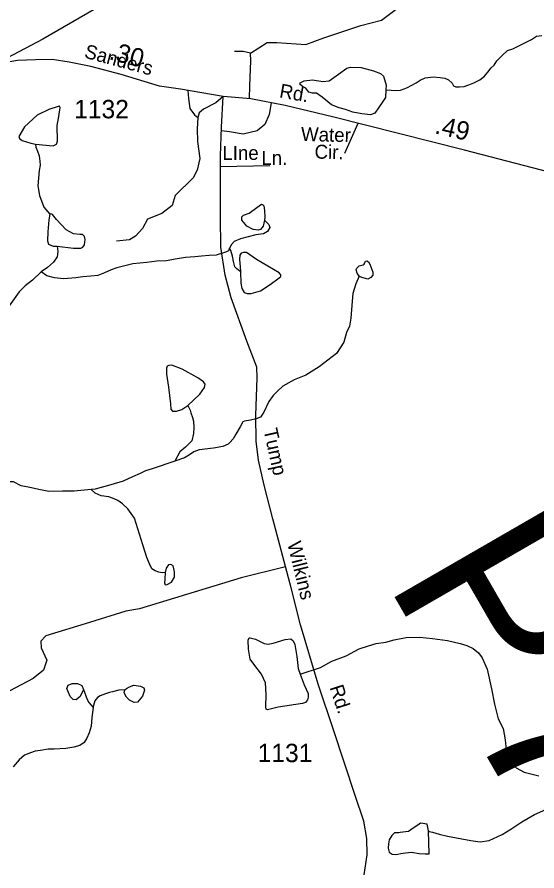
# Model space of a CAD drawing. Extents: x 2056842 to 2160602, y 826753 to 1016856.
# Drawn here: x 2087343 to 2090876, y 890342 to 896145 of the extents above; entities that cross this region are included whole.
import ezdxf

# ---------------------------------------------------------------- set-up
doc = ezdxf.new("R2010")
doc.units = 0
for name, color, linetype in [('Exist Hydrographic Creek Single Shore', 7, 'Continuous'), ('Exist Hydrographic Misc Water Feature', 7, 'Continuous'), ('Exist Road Non-System Type 51', 7, 'Continuous'), ('Exist Road Non-System Type 51 Label', 7, 'Continuous'), ('Exist Road Secondary Mileage Hundredths English Label', 7, 'Continuous'), ('Exist Road Secondary Structure Pipe Number Label', 7, 'Continuous'), ('Exist Road Secondary Type 51 Attributed', 7, 'Continuous'), ('Exist Road Secondary Type 51 Label', 7, 'Continuous'), ('Exist Road Secondary Type 51 Number Label', 7, 'Continuous')]:
    doc.layers.add(name, color=color, linetype=linetype)

msp = doc.modelspace()

# ---------------------------------------------------------------- linework, layer by layer
at = {"layer": 'Exist Hydrographic Creek Single Shore'}
for points in [[(2087467.1, 895281.8), (2087471, 895261.8), (2087481.1, 895233.8), (2087493.2, 895201.6), (2087497.5, 895165.6), (2087499.5, 895137.7), (2087493.6, 895101.7), (2087482.6, 894998.4), (2087495.1, 894932.3), (2087525, 894853.7), (2087566.2, 894805)], [(2087614.8, 894589.1), (2087725.9, 894575.3), (2087775.8, 894574.1), (2087789.5, 894581.6), (2087800.7, 894597.8), (2087805.7, 894634), (2087800.7, 894654), (2087787, 894666.4), (2087768.3, 894666.4), (2087725.9, 894672.7), (2087676, 894700.1), (2087611.1, 894768.8), (2087583.6, 894803.7), (2087571.2, 894808.7), (2087566.2, 894805)], [(2087614.8, 894589.1), (2087619.8, 894552.9), (2087614.8, 894515.4), (2087591.1, 894478.7), (2087550, 894442.5), (2087506.3, 894413.8)], [(2088787, 894573.6), (2088779, 894555.8), (2088766.9, 894550), (2088745.2, 894541.9), (2088695.2, 894527.5), (2088647.4, 894525.5), (2088595.3, 894519.1), (2088551.2, 894515.2), (2088487.3, 894510.8), (2088417.1, 894498.7), (2088357.2, 894488.7), (2088293.3, 894486.2), (2088225.6, 894478.2), (2088129.4, 894467.6), (2088021.4, 894441.4), (2087981.8, 894427.6), (2087937.5, 894407.5), (2087891.6, 894389.2), (2087843.4, 894383.2), (2087789.9, 894380.7), (2087741.9, 894372.6), (2087657.2, 894366.4), (2087596.1, 894372.6), (2087543.7, 894386.4), (2087506.3, 894413.8)], [(2087506.3, 894413.8), (2087447.7, 894356.4), (2087397, 894318.2), (2087357.1, 894278.3), (2087288.5, 894182.2), (2087262.3, 894139.7), (2087220.9, 893995), (2087205.3, 893934.9), (2087189.5, 893870.7), (2087172.5, 893820.2), (2087144.3, 893767)], [(2089667.1, 894384.4), (2089644.7, 894331.9), (2089624.7, 894265.8), (2089619.7, 894214.4), (2089612.2, 894098.3), (2089602.3, 894044.3), (2089582.6, 894000.2), (2089563.2, 893936.1), (2089513.1, 893858.1), (2089396.7, 893767.3), (2089305.6, 893712.4), (2089227, 893679.9), (2089149.7, 893636.2), (2089112, 893602.8), (2089082.3, 893572.8), (2089054.4, 893532.8), (2089020.4, 893458.9), (2088996.8, 893426.7), (2088968.3, 893414.4), (2088928.9, 893404.5), (2088888.7, 893398.5), (2088876.6, 893394.2), (2088858.6, 893360.5), (2088829.1, 893310.1), (2088811, 893277.9), (2088789.1, 893254.1), (2088777.4, 893242), (2088741.1, 893225.6), (2088677.3, 893215.9), (2088581.4, 893203.2), (2088543.2, 893191.2), (2088513.7, 893169.2), (2088479.6, 893148.7), (2088415.9, 893126.2)], [(2087846.3, 892933.2), (2087730.2, 892922.8), (2087650.2, 892922.4), (2087558.2, 892920.1), (2087502.4, 892932.2), (2087430.2, 892947), (2087370.3, 892959.5), (2087319.2, 892985.7), (2087273, 892986.9), (2087230.6, 892968.2), (2087206.9, 892957), (2087139.6, 892976.9), (2087061, 893035.6), (2087029.8, 893053.1), (2086968, 893066.3), (2086820.5, 893090.3)], [(2088415.9, 893126.2), (2088259.8, 893074.2), (2088216, 893060.2), (2088179.7, 893042.1), (2088128, 893020), (2088063.8, 892991.9), (2087980.2, 892965.6), (2087874.1, 892937.1), (2087846.3, 892933.2)], [(2089265.9, 891678.6), (2089404.4, 891724.8), (2089483, 891767.2), (2089579.6, 891804.5), (2089667.5, 891850.8), (2089731.3, 891871.2), (2089783.2, 891887.3), (2089849, 891897.5), (2089905.4, 891911.8), (2089987, 891927.8), (2090080.9, 891930.1), (2090167.2, 891922.3), (2090268.9, 891908.6), (2090353.4, 891887.3), (2090399.2, 891873), (2090443.4, 891853.3), (2090479.3, 891823.5), (2090503.3, 891789.5), (2090537.1, 891714), (2090567, 891580.5), (2090587, 891474.4), (2090613.2, 891374.5), (2090645.6, 891310.9), (2090659.3, 891232.2), (2090669.3, 891141.1), (2090672.6, 891119.4), (2090683.8, 891095.7), (2090734.9, 891043.3), (2090789.8, 891013.3), (2090888.4, 890987.1)], [(2087858.8, 891453.5), (2087851.2, 891385.2), (2087845.4, 891325.2), (2087833.3, 891281.1), (2087817.8, 891243.3), (2087797.7, 891215.1), (2087769.8, 891195), (2087727.7, 891182.7), (2087673.8, 891174.7), (2087593.6, 891168.6), (2087553.6, 891168.6), (2087501.8, 891160.1), (2087465.7, 891155.8), (2087434.1, 891144.1), (2087393.9, 891127.9), (2087355.8, 891097.9), (2087316.4, 891049.5)], [(2090138.9, 890614.7), (2090143.5, 890610.4), (2090167, 890604.8), (2090211.5, 890590.7), (2090269.4, 890579.1), (2090427.2, 890549.5), (2090491.4, 890539.4), (2090551.3, 890549.7), (2090639.3, 890590), (2090698.9, 890626.4), (2090773, 890676.4), (2090860.5, 890724.8), (2090936.8, 890758.8), (2090996.7, 890761), (2091044.7, 890753.3), (2091102.7, 890737), (2091138.9, 890730.7)]]:
    msp.add_lwpolyline(points, dxfattribs=at)
at = {"layer": 'Exist Hydrographic Misc Water Feature'}
for points in [[(2089850.2, 895651.5), (2089921.6, 895645.3), (2089949.5, 895649.4), (2089973.5, 895657.5), (2089997.5, 895665.6), (2090021.5, 895679.6), (2090055.5, 895697.7), (2090083.4, 895715.8), (2090115.4, 895731.9), (2090171.3, 895740.1), (2090219.3, 895734.2), (2090251.3, 895730.2), (2090275.3, 895718.5), (2090299.5, 895696.5), (2090309.3, 895678.5), (2090325.3, 895670.6), (2090349.3, 895670.6), (2090381.5, 895672.7), (2090413.5, 895684.8), (2090447.3, 895698.9), (2090487.3, 895719.1), (2090519.1, 895743.2), (2090543.1, 895771.3), (2090565, 895799.2), (2090584.9, 895819.3), (2090604.8, 895847.4), (2090640.7, 895883.5), (2090676.6, 895917.6), (2090712.5, 895929.8), (2090838.4, 895992.1), (2090874.3, 896016.2), (2090910.4, 896020.4)], [(2089850.2, 895651.5), (2089847.8, 895599), (2089825.3, 895564.1), (2089774.2, 895492.9), (2089744.2, 895480.5), (2089686.8, 895487.9), (2089625.7, 895497.9), (2089575.8, 895517.9), (2089532.1, 895527.9), (2089479.8, 895547.9), (2089417.4, 895601.5), (2089377.5, 895627.7), (2089351.3, 895627.7), (2089325.1, 895635.2), (2089306.4, 895661.4), (2089282.7, 895673.9), (2089265.2, 895690.1), (2089267.7, 895698.9), (2089293.9, 895712.6), (2089350, 895718.9), (2089421.1, 895707.6), (2089464.8, 895711.4), (2089527.2, 895756.3), (2089583.3, 895798.7), (2089609.5, 895805), (2089681.8, 895802.5), (2089764.2, 895778.8), (2089812.8, 895761.3), (2089832.8, 895742.6), (2089851.5, 895681.4), (2089850.2, 895651.5)], [(2087467.1, 895281.8), (2087587.4, 895270.3), (2087609.8, 895281.5), (2087617.3, 895301.5), (2087616.1, 895407.6), (2087626.1, 895468.7), (2087634.8, 895529.9), (2087629.8, 895539.9), (2087622.3, 895537.4), (2087558.7, 895517.4), (2087478.9, 895478.7), (2087394, 895400.1), (2087354.1, 895333.9), (2087357.9, 895320.2), (2087376.6, 895306.5), (2087436.4, 895287.8), (2087467.1, 895281.8)], [(2089024.5, 894764.5), (2089014.5, 894723.1), (2088997, 894701.9), (2088980.8, 894696.9), (2088947.1, 894700.6), (2088904.7, 894723.1), (2088871, 894765.5), (2088869.8, 894788), (2088882.2, 894799.2), (2088919.7, 894813), (2088972, 894850.4), (2089003.2, 894872.9), (2089010.7, 894871.6), (2089019.4, 894861.6), (2089024.4, 894830.4), (2089025.7, 894784.3), (2089024.5, 894764.5)], [(2087566.2, 894805), (2087558.7, 894766.3), (2087552.5, 894686.4), (2087550, 894624), (2087556.2, 894601.5), (2087587.4, 894587.8), (2087614.8, 894589.1)], [(2089024.5, 894764.5), (2089054.4, 894735.8), (2089060.6, 894714.6), (2089044.6, 894688.4), (2089016.9, 894672.7), (2088964.6, 894664.5), (2088912.7, 894652.4), (2088860.7, 894637.9), (2088819, 894620), (2088800.8, 894600), (2088787, 894573.6)], [(2088862.3, 894412.6), (2088845.3, 894428.1), (2088837.5, 894432.1), (2088829.3, 894439.9), (2088823.5, 894448.1), (2088813.3, 894484), (2088806.9, 894519.9), (2088795, 894557.9), (2088787, 894573.6)], [(2088862.3, 894412.6), (2088863.5, 894337.7), (2088869.8, 894300.2), (2088886, 894274), (2088907.2, 894265.3), (2088934.6, 894265.3), (2088998.2, 894285.3), (2089063.1, 894327.7), (2089123, 894372.6), (2089135.5, 894382.6), (2089135.5, 894392.6), (2089124.2, 894406.3), (2088970.8, 894497.4), (2088902.2, 894544.9), (2088881, 894546.1), (2088866, 894541.1), (2088856, 894526.1), (2088854.8, 894497.4), (2088859.8, 894447.5), (2088862.3, 894412.6)], [(2089667.1, 894384.4), (2089653.4, 894405.6), (2089647.2, 894426.8), (2089650.9, 894438), (2089667.1, 894455.5), (2089694.6, 894460.5), (2089702, 894466.7), (2089712, 894486.7), (2089720.8, 894489.2), (2089730.7, 894480.5), (2089739.5, 894465.5), (2089760.7, 894410.6), (2089760.7, 894391.8), (2089747, 894374.4), (2089725.8, 894364.4), (2089687.1, 894374.4), (2089667.1, 894384.4)], [(2088503.3, 893504.4), (2088584.3, 893583), (2088616.8, 893626.7), (2088621.8, 893650.4), (2088610.5, 893665.4), (2088571.9, 893692.9), (2088464.6, 893752.8), (2088393.5, 893779), (2088374.8, 893777.8), (2088363.5, 893771.5), (2088358.6, 893759), (2088357.3, 893719.1), (2088372.3, 893629.2), (2088384.8, 893515.6), (2088388.5, 893479.4), (2088398.5, 893467), (2088401, 893467), (2088427.2, 893465.7), (2088462.1, 893477), (2088503.3, 893504.4)], [(2088503.3, 893504.4), (2088519.5, 893473.2), (2088523.2, 893454.5), (2088534.4, 893423.3), (2088540.7, 893399.6), (2088544.4, 893355.9), (2088541.9, 893315.9), (2088529.5, 893264.8), (2088487, 893222.3), (2088448.4, 893191.1), (2088415.9, 893126.2)], [(2088348.8, 892369.3), (2088329.8, 892368.5), (2088305.8, 892372.5), (2088282, 892380.6), (2088258, 892394.4), (2088242, 892428.5), (2088225.6, 892472.4), (2088196.6, 892559.1), (2088164.2, 892667.7), (2088141.8, 892738.8), (2088094.8, 892801.8), (2088058.3, 892835.7), (2088028.3, 892859.7), (2088002.7, 892871.7), (2087966.2, 892885.4), (2087914.1, 892891.3), (2087874.1, 892909.1), (2087846.3, 892933.2)], [(2088348.8, 892369.3), (2088347.6, 892325.7), (2088345.1, 892299.4), (2088350.1, 892287), (2088363.8, 892288.2), (2088392.5, 892304.4), (2088413.7, 892338.1), (2088413.7, 892374.3), (2088403.7, 892414.3), (2088387.5, 892424.3), (2088372.5, 892421.8), (2088355.1, 892399.3), (2088348.8, 892369.3)], [(2089265.9, 891678.6), (2089294.6, 891606.2), (2089320.8, 891547.5), (2089322.1, 891523.8), (2089317.1, 891503.8), (2089303.4, 891486.4), (2089283.4, 891478.9), (2089116.3, 891453.9), (2089043.9, 891436.4), (2089036.4, 891440.2), (2089032.7, 891456.4), (2089036.4, 891540), (2089030.2, 891621.2), (2089004, 891678.6), (2088951.6, 891746), (2088926.6, 891780.9), (2088915.4, 891848.3), (2088914.2, 891909.5), (2088920.4, 891927), (2088926.6, 891927), (2088962.8, 891917), (2089022.7, 891888.3), (2089048.9, 891883.3), (2089083.8, 891889.5), (2089164.9, 891914.5), (2089203.6, 891918.2), (2089219.8, 891905.7), (2089231, 891880.8), (2089244.7, 891799.7), (2089252.2, 891718.5), (2089265.9, 891678.6)], [(2087794.4, 891575.2), (2087772.3, 891526.3), (2087743.6, 891503.9), (2087723.6, 891506.4), (2087702.4, 891526.3), (2087679.9, 891581.3), (2087689.9, 891605), (2087716.1, 891615), (2087752.3, 891616.2), (2087783.5, 891602.5), (2087794.4, 891575.2)], [(2087794.4, 891575.2), (2087818.8, 891507), (2087830.7, 891487.3), (2087846.9, 891469.4), (2087858.8, 891453.5)], [(2088074.3, 891572.1), (2088034.5, 891570), (2087990.2, 891559.7), (2087970.5, 891553.7), (2087942.8, 891545.3), (2087906.5, 891531.4), (2087888.7, 891521.6), (2087870.7, 891497), (2087862.9, 891465.4), (2087858.8, 891453.5)], [(2088074.3, 891572.1), (2088085.4, 891582.5), (2088106.6, 891593.7), (2088136.5, 891603.7), (2088181.4, 891597.5), (2088203.9, 891586.3), (2088207.6, 891570), (2088195.1, 891528.8), (2088160.2, 891488.9), (2088139, 891486.4), (2088106.6, 891501.4), (2088086.6, 891523.9), (2088070.4, 891552.6), (2088074.3, 891572.1)], [(2090138.9, 890614.7), (2090130.9, 890658.5), (2090085, 890666.3), (2090067, 890652.3), (2090035.2, 890632), (2090003, 890610.1), (2089983.1, 890607.8), (2089947.2, 890603.9), (2089937.6, 890601.8), (2089907, 890599.9), (2089889.4, 890583.5), (2089871.4, 890553.4), (2089867.5, 890525.6), (2089865.8, 890497.4), (2089871.8, 890469.7), (2089891.7, 890455.8), (2089911.5, 890453.5), (2089931.4, 890455.8), (2089951.7, 890460.1), (2089967.7, 890462), (2089983.9, 890464.1), (2090023.7, 890468.2), (2090075.4, 890460.4), (2090116, 890458.4), (2090143.7, 890458.6), (2090138.9, 890614.7)]]:
    msp.add_lwpolyline(points, dxfattribs=at)
at = {"layer": 'Exist Road Non-System Type 51'}
msp.add_line((2088725.1, 895129.6), (2089060.1, 895137.2), dxfattribs=at)
for points in [[(2088929, 895898.9), (2089042.3, 895971.9), (2089109.3, 895973.4), (2089305.9, 895958.5), (2089426.6, 896004.7), (2089679, 896089), (2089820.6, 896124.7), (2089947.2, 896220.1), (2090026.9, 896286.5), (2090080.5, 896302.9)], [(2088929, 895898.9), (2088879.9, 895910.8), (2088820.3, 895910.8)], [(2088922.6, 895591.3), (2088924.6, 895678.3), (2088932, 895846.7), (2088929, 895898.9)], [(2088502.9, 895646.6), (2088506.8, 895591.1), (2088517.2, 895524), (2088548.5, 895480.8), (2088572.3, 895462.9)], [(2088742.6, 895606), (2088694.4, 895562.8), (2088609.5, 895519.6), (2088581.2, 895494.2), (2088572.3, 895462.9)], [(2089069.2, 895562.9), (2089057.1, 895483), (2089027.4, 895416), (2088973.7, 895371.2), (2088878.4, 895348.9), (2088787.5, 895365.3), (2088731.7, 895371.5)], [(2088572.3, 895462.9), (2088566.3, 895385.4), (2088569.3, 895300.4), (2088585, 895184.9), (2088565.6, 895104.4), (2088540.3, 895052.3), (2088416.6, 894933), (2088397.3, 894864.4), (2088326.5, 894810), (2088229.7, 894771.3), (2088195.4, 894707.2), (2088147.8, 894655), (2088106.1, 894631.2), (2088018.2, 894622.2)], [(2089570.6, 895220.2), (2089661.6, 895423.3)], [(2089168, 892407.5), (2088866.3, 892333.8), (2088175.1, 892122.1), (2088082.8, 892107.2), (2087835.5, 892029.7), (2087539.1, 891938.8), (2087503.3, 891903), (2087506.3, 891858.3), (2087545, 891774.8), (2087521.2, 891706.2), (2087452.7, 891649.6), (2087127.9, 891479.7), (2087065.4, 891420), (2086928.3, 891279.9), (2086676.6, 891054.8), (2086036, 890574.8), (2085937.7, 890551)]]:
    msp.add_lwpolyline(points, dxfattribs=at)
at = {"layer": 'Exist Road Secondary Type 51 Attributed'}
for points in [[(2097584.5, 901381.1), (2097440.8, 901258.9), (2097275.5, 901120.4), (2097046.5, 900979.3), (2096312.6, 900635.1), (2095454.9, 900254.9), (2094879.1, 899939.4), (2094260.3, 899562.8), (2093814.7, 899296.7), (2093533.6, 899171.8), (2092778.2, 898906.6), (2092463.9, 898789.7), (2091981.5, 898576.7), (2091780.3, 898463.5), (2091132.7, 898086.9), (2090400.7, 897659.9), (2089683, 897256.3), (2089377.6, 897073), (2088782.1, 896719.7), (2088437.2, 896513), (2087866.9, 896195.7), (2087516.6, 895996.1), (2087189.6, 895823.6)], [(2088742.6, 895606), (2088452.9, 895655), (2088310.1, 895676.6), (2088051, 895754.4), (2087844.4, 895808.3), (2087697.1, 895838.8), (2087582.1, 895856.8), (2087467.2, 895855), (2087345, 895849.6), (2087189.6, 895823.6)], [(2089700.9, 890315.3), (2089722.5, 890451.7), (2089721, 890562), (2089700.2, 890679.8), (2089640.6, 890854.2), (2089492.4, 891300.6), (2089388.1, 891612.1), (2089268.2, 892013.8), (2089205.6, 892265.7), (2089081.2, 892734.5), (2089021.7, 892962.6), (2088982.9, 893132.5), (2088968, 893262.2), (2088965.8, 893437.4), (2088974.7, 893692.2), (2088973.2, 893766.8), (2088904, 893943.4), (2088798.2, 894237.1), (2088756.5, 894390.6), (2088727.5, 894582.1), (2088724.5, 894784.9), (2088725.2, 895203), (2088732.7, 895396.7), (2088742.6, 895606)], [(2091253.5, 894999.7), (2091021.7, 895075.2), (2090383.1, 895241.5), (2089487.6, 895467.1), (2089164.2, 895544.4), (2088932.5, 895589.4), (2088742.6, 895606)]]:
    msp.add_lwpolyline(points, dxfattribs=at)

# ---------------------------------------------------------------- texts
at = {"layer": 'Exist Road Non-System Type 51 Label'}
for s, p in [('Water', (2089271.7, 895303)), ('Cir.', (2089363.7, 895183.4))]:
    msp.add_text(s, height=95, rotation=358.63518, dxfattribs=at).set_placement(p)
for s, p in [('LIne', (2088737.8, 895174.5)), ('Ln.', (2089002.9, 895140.7))]:
    msp.add_text(s, height=95, dxfattribs=at).set_placement(p)
at = {"layer": 'Exist Road Secondary Mileage Hundredths English Label'}
for s, rotation, p in [('.30', 344.94495, (2087961.7, 895860.2)), ('.49', 346.9198, (2090176, 895355.9))]:
    msp.add_text(s, height=125, rotation=rotation, dxfattribs=at).set_placement(p)
at = {"layer": 'Exist Road Secondary Structure Pipe Number Label'}
msp.add_text('P77', height=1230.31, rotation=300, dxfattribs=at).set_placement((2089841, 892319.4))
at = {"layer": 'Exist Road Secondary Type 51 Label'}
for s, rotation, p in [('Sanders', 344.94497, (2087794, 895870.6)), ('Rd.', 349.95696, (2089121.1, 895599.9)), ('Tump', 282.44939, (2089016.9, 893339.7)), ('Wilkins', 283.76334, (2089178.5, 892568.4)), ('Rd.', 287.97283, (2089466, 891589.4))]:
    msp.add_text(s, height=95, rotation=rotation, dxfattribs=at).set_placement(p)
at = {"layer": 'Exist Road Secondary Type 51 Number Label'}
for s, p in [('1132', (2087730.7, 895457.1)), ('1131', (2088978, 891081.1))]:
    msp.add_text(s, height=125, dxfattribs=at).set_placement(p)

doc.saveas('drawing.dxf')
